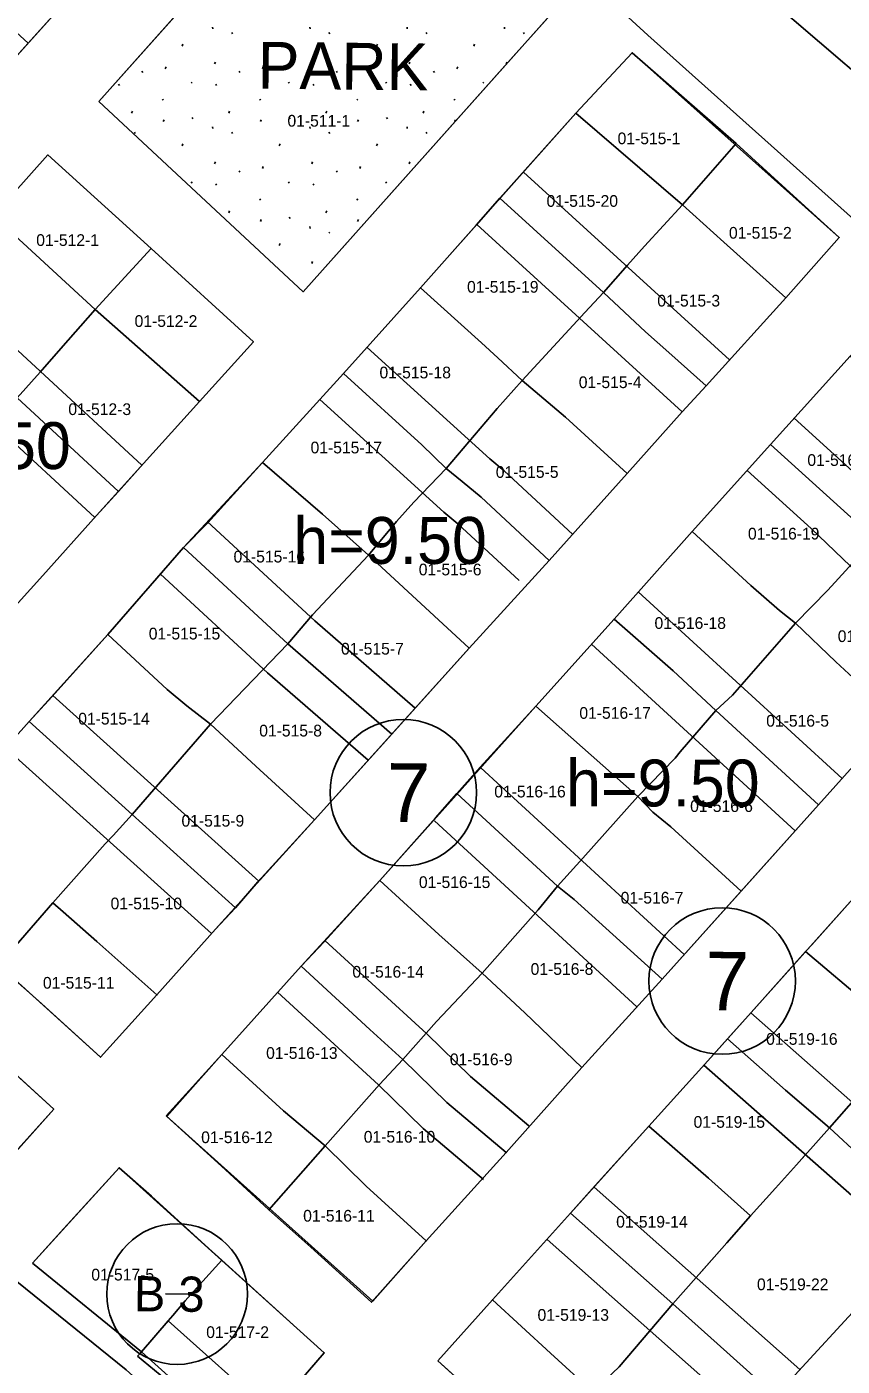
# Model space of a CAD drawing. Extents: x 413946 to 415528, y 4453939 to 4454944.
# Drawn here: x 415275 to 415344.5, y 4454500.5 to 4454614.8 of the extents above; entities that cross this region are included whole.
import ezdxf

# ---------------------------------------------------------------- set-up
doc = ezdxf.new("R2010")
doc.units = 0
for name, color, linetype in [('0_KADASTRO', 7, 'Continuous'), ('Level 27', 7, 'Continuous'), ('Level 28', 7, 'Continuous'), ('Level 30', 7, 'Continuous'), ('Level 32', 7, 'Continuous'), ('Level 41', 7, 'Continuous'), ('Level 58', 7, 'Continuous'), ('Level 59', 7, 'Continuous'), ('Level 62', 7, 'Continuous')]:
    doc.layers.add(name, color=color, linetype=linetype)

msp = doc.modelspace()

# ---------------------------------------------------------------- linework, layer by layer
at = {"layer": '0_KADASTRO'}
for points in [[(415281.1, 4454608.41), (415300.49, 4454630.14), (415303.6, 4454633.63), (415321.18, 4454617.54), (415316.45, 4454612.24), (415298.54, 4454592.17)], [(415264.52, 4454619), (415268.19, 4454623.21), (415271.06, 4454626.51), (415275.41, 4454622.61), (415279.81, 4454618.66), (415275.06, 4454613.36), (415273.08, 4454611.16)], [(415321.81, 4454607.4), (415326.6, 4454612.57), (415335.47, 4454604.83), (415330.89, 4454599.59)], [(415315.33, 4454600.15), (415321.81, 4454607.4), (415330.89, 4454599.59), (415327.65, 4454596.07), (415326.22, 4454594.45), (415324.15, 4454592.12)], [(415330.89, 4454599.59), (415335.47, 4454604.83), (415344.27, 4454596.8), (415339.71, 4454591.65), (415334.42, 4454596.39)], [(415272.09, 4454598.64), (415276.77, 4454603.85), (415285.57, 4454595.85), (415280.79, 4454590.65)], [(415308.54, 4454592.51), (415313.29, 4454597.85), (415315.33, 4454600.15), (415324.15, 4454592.12), (415322.56, 4454590.39), (415317.23, 4454584.6), (415315.14, 4454586.52), (415313.75, 4454587.8)], [(415324.15, 4454592.12), (415326.22, 4454594.45), (415327.65, 4454596.07), (415330.89, 4454599.59), (415334.42, 4454596.39), (415339.71, 4454591.65), (415332.91, 4454584.14), (415329.74, 4454586.98), (415327.75, 4454588.74)], [(415265.41, 4454591.2), (415267.45, 4454593.47), (415272.09, 4454598.64), (415280.79, 4454590.65), (415277.86, 4454587.32), (415276.1, 4454585.32), (415274.15, 4454583.11)], [(415280.79, 4454590.65), (415285.57, 4454595.85), (415294.3, 4454587.9), (415289.71, 4454582.81)], [(415301.97, 4454585.2), (415308.54, 4454592.51), (415313.75, 4454587.8), (415315.14, 4454586.52), (415317.23, 4454584.6), (415315.09, 4454582.21), (415310.75, 4454577.08), (415308.66, 4454579.12)], [(415317.23, 4454584.6), (415322.56, 4454590.39), (415324.15, 4454592.12), (415327.75, 4454588.74), (415329.74, 4454586.98), (415332.91, 4454584.14), (415330.87, 4454581.92), (415326.17, 4454576.67), (415320.92, 4454581.48)], [(415274.15, 4454583.11), (415276.1, 4454585.32), (415277.86, 4454587.32), (415280.79, 4454590.65), (415289.71, 4454582.81), (415284.92, 4454577.51), (415282.78, 4454575.13)], [(415338.41, 4454579.14), (415345.19, 4454586.67), (415352.4, 4454579.91), (415353.71, 4454578.68), (415347.21, 4454571), (415345.81, 4454572.43), (415345.58, 4454572.64)], [(415295.06, 4454577.59), (415301.97, 4454585.2), (415308.66, 4454579.12), (415310.75, 4454577.08), (415307.98, 4454574.21), (415306.51, 4454572.56), (415304.12, 4454569.7), (415300.18, 4454573.19)], [(415310.75, 4454577.08), (415315.09, 4454582.21), (415317.23, 4454584.6), (415320.92, 4454581.48), (415326.17, 4454576.67), (415319.51, 4454569.25), (415313.71, 4454574.63), (415312.09, 4454575.97)], [(415263.01, 4454570.8), (415260.8, 4454568.32), (415264.13, 4454565.29), (415266.34, 4454563.27), (415269.49, 4454560.4), (415276.32, 4454567.97), (415280.92, 4454573.07), (415282.78, 4454575.13), (415282.78, 4454575.13), (415282.78, 4454575.13), (415274.15, 4454583.11), (415270.75, 4454579.39), (415267.56, 4454575.9), (415264.2, 4454572.13)], [(415331.71, 4454571.7), (415338.41, 4454579.14), (415345.58, 4454572.64), (415345.81, 4454572.43), (415347.21, 4454571), (415343.29, 4454566.72), (415340.55, 4454563.89), (415339.16, 4454564.98), (415336.73, 4454567.11)], [(415288.34, 4454570.34), (415290.4, 4454572.44), (415295.06, 4454577.59), (415300.18, 4454573.19), (415304.12, 4454569.7), (415299.34, 4454564.59), (415297.22, 4454562.12), (415295.82, 4454563.43)], [(415304.12, 4454569.7), (415306.51, 4454572.56), (415307.98, 4454574.21), (415310.75, 4454577.08), (415312.09, 4454575.97), (415313.71, 4454574.63), (415319.51, 4454569.25), (415312.71, 4454561.76)], [(415325.06, 4454564.24), (415331.71, 4454571.7), (415336.73, 4454567.11), (415339.16, 4454564.98), (415340.55, 4454563.89), (415335.17, 4454557.74), (415333.75, 4454556.43), (415330.11, 4454559.82)], [(415281.87, 4454562.92), (415288.34, 4454570.34), (415295.82, 4454563.43), (415297.22, 4454562.12), (415290.64, 4454555.26), (415288.63, 4454556.85), (415286.94, 4454558.24)], [(415340.55, 4454563.89), (415343.29, 4454566.72), (415347.21, 4454571), (415350.59, 4454567.77), (415355.89, 4454563.36), (415349.15, 4454555.82), (415343.97, 4454560.6)], [(415297.22, 4454562.12), (415299.34, 4454564.59), (415304.12, 4454569.7), (415312.71, 4454561.76), (415306.1, 4454554.42)], [(415318.4, 4454556.81), (415325.06, 4454564.24), (415330.11, 4454559.82), (415333.75, 4454556.43), (415330.71, 4454552.92), (415330.28, 4454552.36), (415327.09, 4454549.11)], [(415333.75, 4454556.43), (415335.17, 4454557.74), (415340.55, 4454563.89), (415343.97, 4454560.6), (415349.15, 4454555.82), (415342.51, 4454548.4)], [(415275.17, 4454555.49), (415277.14, 4454557.64), (415281.87, 4454562.92), (415286.94, 4454558.24), (415288.63, 4454556.85), (415290.64, 4454555.26), (415283.96, 4454547.56)], [(415290.64, 4454555.26), (415297.22, 4454562.12), (415306.1, 4454554.42), (415299.5, 4454547.12), (415294.49, 4454551.68)], [(415311.65, 4454549.35), (415313.65, 4454551.59), (415318.4, 4454556.81), (415327.09, 4454549.11), (415322.41, 4454543.84), (415320.23, 4454541.46)], [(415263.74, 4454542.72), (415268.39, 4454547.93), (415275.17, 4454555.49), (415283.96, 4454547.56), (415282.32, 4454545.78), (415281.66, 4454545.07), (415277.2, 4454540.02), (415272.54, 4454534.71)], [(415327.09, 4454549.11), (415330.28, 4454552.36), (415330.71, 4454552.92), (415333.75, 4454556.43), (415342.51, 4454548.4), (415335.9, 4454541.03), (415329.91, 4454546.51), (415328.37, 4454547.75)], [(415283.96, 4454547.56), (415290.64, 4454555.26), (415294.49, 4454551.68), (415299.5, 4454547.12), (415294.67, 4454541.81), (415292.77, 4454539.6)], [(415305.09, 4454541.94), (415309.83, 4454547.27), (415311.65, 4454549.35), (415320.23, 4454541.46), (415318.58, 4454539.44), (415313.8, 4454534.03), (415310.1, 4454537.32)], [(415320.23, 4454541.46), (415322.41, 4454543.84), (415327.09, 4454549.11), (415328.37, 4454547.75), (415329.91, 4454546.51), (415335.9, 4454541.03), (415329.15, 4454533.51), (415321.67, 4454540.3)], [(415277.2, 4454540.02), (415281.66, 4454545.07), (415282.32, 4454545.78), (415283.96, 4454547.56), (415292.77, 4454539.6), (415291.06, 4454537.79), (415286.06, 4454532.17), (415280.93, 4454536.74), (415278.08, 4454539.25)], [(415341.4, 4454535.86), (415341.92, 4454536.44), (415346.16, 4454541.18), (415348.08, 4454543.29), (415352.98, 4454538.72), (415356.69, 4454535.4), (415354.88, 4454533.47), (415350.02, 4454528.33), (415346.7, 4454531.38)], [(415298.37, 4454534.61), (415300.32, 4454536.7), (415305.09, 4454541.94), (415310.1, 4454537.32), (415313.8, 4454534.03), (415309.92, 4454529.9), (415307.04, 4454526.66), (415304.24, 4454529.22)], [(415313.8, 4454534.03), (415318.58, 4454539.44), (415320.23, 4454541.46), (415321.67, 4454540.3), (415329.15, 4454533.51), (415327.16, 4454531.33), (415322.3, 4454525.96), (415317.45, 4454530.63)], [(415272.54, 4454534.71), (415277.2, 4454540.02), (415278.08, 4454539.25), (415280.93, 4454536.74), (415286.06, 4454532.17), (415281.26, 4454526.85), (415276.21, 4454531.43), (415273.47, 4454533.88)], [(415334.73, 4454528.41), (415336.75, 4454530.66), (415341.4, 4454535.86), (415346.7, 4454531.38), (415350.02, 4454528.33), (415343.44, 4454520.82), (415339.68, 4454524.05)], [(415291.59, 4454527.07), (415298.37, 4454534.61), (415304.24, 4454529.22), (415307.04, 4454526.66), (415305.05, 4454524.51), (415300.43, 4454519.28), (415296.85, 4454522.27)], [(415307.04, 4454526.66), (415309.92, 4454529.9), (415313.8, 4454534.03), (415317.45, 4454530.63), (415322.3, 4454525.96), (415315.86, 4454518.71), (415310.8, 4454522.99)], [(415260.25, 4454521.48), (415262.84, 4454524.11), (415268.59, 4454530.33), (415269.76, 4454529.25), (415272.17, 4454527.05), (415277.27, 4454522.42), (415272.6, 4454517.21), (415269.64, 4454513.87)], [(415328.03, 4454520.98), (415332.79, 4454526.26), (415334.73, 4454528.41), (415339.68, 4454524.05), (415343.44, 4454520.82), (415341.32, 4454518.46), (415340.61, 4454517.67), (415338.82, 4454515.67), (415336.69, 4454513.32), (415333.11, 4454516.54)], [(415343.44, 4454520.82), (415350.02, 4454528.33), (415358.94, 4454520.32), (415354.15, 4454514.93), (415352.33, 4454512.88), (415346.15, 4454518.33)], [(415286.9, 4454521.8), (415291.59, 4454527.07), (415296.85, 4454522.27), (415300.43, 4454519.28), (415295.61, 4454513.84), (415291.88, 4454517.27)], [(415300.43, 4454519.28), (415305.05, 4454524.51), (415307.04, 4454526.66), (415310.8, 4454522.99), (415315.86, 4454518.71), (415309.04, 4454511.18), (415303.91, 4454515.86)], [(415321.35, 4454513.54), (415323.19, 4454515.61), (415328.03, 4454520.98), (415333.11, 4454516.54), (415336.69, 4454513.32), (415334.67, 4454511.02), (415332.05, 4454508.05), (415330.07, 4454505.8)], [(415341.28, 4454518.41), (415340.61, 4454517.67), (415338.82, 4454515.67), (415336.69, 4454513.32), (415334.67, 4454511.02), (415332.54, 4454508.6), (415332.05, 4454508.05), (415330.07, 4454505.8), (415333.85, 4454502.42), (415338.85, 4454497.94), (415340.8, 4454500.07), (415345.71, 4454505.4), (415352.33, 4454512.88), (415346.15, 4454518.33), (415343.44, 4454520.82), (415341.32, 4454518.46)], [(415295.61, 4454513.84), (415300.43, 4454519.28), (415303.91, 4454515.86), (415309.04, 4454511.18), (415304.38, 4454505.94), (415299.18, 4454510.63)], [(415275.45, 4454509.28), (415284.74, 4454501.7), (415287.02, 4454504.37), (415287.41, 4454504.82), (415288.47, 4454506.05), (415289.44, 4454507.13), (415291.61, 4454509.52), (415290.5, 4454510.53), (415285.61, 4454514.99), (415282.84, 4454517.42), (415278.13, 4454512.24)], [(415314.69, 4454506.15), (415321.35, 4454513.54), (415330.07, 4454505.8), (415325.5, 4454500.43), (415323.26, 4454498.3), (415319.65, 4454501.61)], [(415287.02, 4454504.37), (415287.41, 4454504.82), (415288.47, 4454506.05), (415289.44, 4454507.13), (415291.61, 4454509.52), (415298, 4454503.73), (415300.34, 4454501.63), (415295.86, 4454496.44)], [(415310.02, 4454500.93), (415314.69, 4454506.15), (415319.65, 4454501.61), (415323.26, 4454498.3), (415318.7, 4454493.11)], [(415323.26, 4454498.3), (415325.5, 4454500.43), (415330.07, 4454505.8), (415333.85, 4454502.42), (415338.85, 4454497.94), (415336.86, 4454495.7), (415332.18, 4454490.43)], [(415284.42, 4454501.33), (415284.64, 4454501.58), (415284.74, 4454501.7), (415287.02, 4454504.37), (415295.86, 4454496.44), (415293.58, 4454493.77)]]:
    msp.add_lwpolyline(points, close=True, dxfattribs=at)
at = {"layer": 'Level 27'}
for p, q in [((415326.6, 4454612.57), (415344.27, 4454596.8)), ((415298.54, 4454592.17), (415281.1, 4454608.41)), ((415281.26, 4454526.85), (415263.74, 4454542.72)), ((415259.8, 4454538.31), (415277.27, 4454522.42)), ((415304.47, 4454506.04), (415286.85, 4454521.84)), ((415282.84, 4454517.42), (415300.34, 4454501.63)), ((415327.52, 4454485.21), (415310.02, 4454500.93))]:
    msp.add_line(p, q, dxfattribs=at)
for points in [[(415263.74, 4454542.72), (415268.39, 4454547.93), (415275.17, 4454555.49), (415281.87, 4454562.92), (415288.34, 4454570.34), (415295.06, 4454577.59), (415301.97, 4454585.2), (415308.54, 4454592.51), (415321.81, 4454607.4), (415326.6, 4454612.57)], [(415240.66, 4454563.64), (415245.43, 4454568.95), (415250.05, 4454574.1), (415254.04, 4454578.54), (415265.41, 4454591.2), (415267.45, 4454593.47), (415272.09, 4454598.64), (415276.77, 4454603.85), (415285.57, 4454595.85), (415294.3, 4454587.9), (415289.71, 4454582.81), (415284.92, 4454577.51), (415280.92, 4454573.07), (415276.32, 4454567.97), (415269.49, 4454560.4), (415262.86, 4454553.06), (415258.15, 4454547.84)], [(415344.27, 4454596.8), (415339.71, 4454591.65), (415332.91, 4454584.14), (415330.87, 4454581.92), (415326.17, 4454576.67), (415319.51, 4454569.25), (415312.71, 4454561.76), (415299.5, 4454547.12), (415291.06, 4454537.79), (415286.06, 4454532.17), (415281.26, 4454526.85)], [(415286.85, 4454521.84), (415291.59, 4454527.07), (415298.37, 4454534.61), (415305.09, 4454541.94), (415318.4, 4454556.81), (415325.06, 4454564.24), (415331.71, 4454571.7), (415338.41, 4454579.14), (415345.19, 4454586.67), (415349.81, 4454591.81)], [(415367.29, 4454575.96), (415362.62, 4454570.74), (415355.89, 4454563.36), (415349.15, 4454555.82), (415342.51, 4454548.4), (415329.15, 4454533.51), (415322.3, 4454525.96), (415315.86, 4454518.71), (415309.04, 4454511.18), (415304.47, 4454506.04)], [(415310.02, 4454500.93), (415314.69, 4454506.15), (415321.35, 4454513.54), (415328.03, 4454520.98), (415332.79, 4454526.26), (415336.75, 4454530.66), (415346.16, 4454541.18), (415354.8, 4454550.86), (415361.66, 4454558.38), (415368.28, 4454565.86), (415372.83, 4454571.21)], [(415390.31, 4454555.19), (415385.34, 4454549.56), (415378.94, 4454542.48), (415372.27, 4454535.1), (415363.68, 4454525.56), (415358.94, 4454520.32), (415352.33, 4454512.88), (415345.71, 4454505.4), (415340.8, 4454500.07), (415336.86, 4454495.7), (415332.18, 4454490.43), (415327.52, 4454485.21)], [(415277.27, 4454522.42), (415269.59, 4454513.91)], [(415275.45, 4454509.28), (415282.84, 4454517.42)], [(415293.57, 4454493.78), (415284.74, 4454501.7), (415275.45, 4454509.28)], [(415300.34, 4454501.63), (415293.57, 4454493.78)]]:
    msp.add_lwpolyline(points, dxfattribs=at)
at = {"layer": 'Level 28'}
for p, q in [((415281.1, 4454608.41), (415303.6, 4454633.63)), ((415321.18, 4454617.54), (415298.54, 4454592.17))]:
    msp.add_line(p, q, dxfattribs=at)
msp.add_lwpolyline([(415297.91, 4454638.85), (415293.18, 4454633.57), (415286.52, 4454626.14), (415279.81, 4454618.66), (415273.91, 4454612.08)], dxfattribs=at)
at = {"layer": 'Level 32'}
msp.add_line((415288.79, 4454506.63), (415286.79, 4454506.65), dxfattribs=at)
msp.add_circle((415287.79, 4454506.64), 6, dxfattribs=at)
at = {"layer": 'Level 41'}
for p, q in [((415290.82, 4454614.76), (415290.83, 4454614.6)), ((415292.45, 4454614.29), (415292.52, 4454614.18)), ((415299.11, 4454614.76), (415299.13, 4454614.6)), ((415300.74, 4454614.29), (415300.81, 4454614.18)), ((415307.4, 4454614.76), (415307.42, 4454614.6)), ((415309.03, 4454614.29), (415309.1, 4454614.18)), ((415315.7, 4454614.76), (415315.71, 4454614.6)), ((415317.33, 4454614.29), (415317.4, 4454614.18)), ((415288.21, 4454613.14), (415288.28, 4454613.3)), ((415296.5, 4454613.14), (415296.57, 4454613.3)), ((415304.79, 4454613.14), (415304.87, 4454613.3)), ((415313.09, 4454613.14), (415313.16, 4454613.3)), ((415290.98, 4454611.61), (415291.05, 4454611.77)), ((415299.27, 4454611.61), (415299.34, 4454611.77)), ((415307.57, 4454611.61), (415307.64, 4454611.77)), ((415315.86, 4454611.61), (415315.93, 4454611.77)), ((415284.78, 4454611), (415284.85, 4454610.89)), ((415286.77, 4454611.2), (415286.84, 4454611.36)), ((415293.08, 4454611), (415293.15, 4454610.89)), ((415295.06, 4454611.2), (415295.14, 4454611.36)), ((415301.37, 4454611), (415301.44, 4454610.89)), ((415303.36, 4454611.2), (415303.43, 4454611.36)), ((415309.66, 4454611), (415309.73, 4454610.89)), ((415311.65, 4454611.2), (415311.72, 4454611.36)), ((415282.8, 4454609.88), (415282.87, 4454609.77)), ((415288.99, 4454610.07), (415289.06, 4454609.96)), ((415291.09, 4454609.88), (415291.16, 4454609.77)), ((415297.28, 4454610.07), (415297.35, 4454609.96)), ((415299.38, 4454609.88), (415299.45, 4454609.77)), ((415305.58, 4454610.07), (415305.65, 4454609.96)), ((415307.68, 4454609.88), (415307.75, 4454609.77)), ((415313.87, 4454610.07), (415313.94, 4454609.96)), ((415286.54, 4454608.61), (415286.61, 4454608.51)), ((415294.83, 4454608.61), (415294.9, 4454608.51)), ((415303.12, 4454608.61), (415303.19, 4454608.51)), ((415311.41, 4454608.61), (415311.48, 4454608.51)), ((415283.89, 4454607.42), (415283.97, 4454607.58)), ((415286.59, 4454606.69), (415286.67, 4454606.85)), ((415289.06, 4454607.04), (415289.13, 4454606.93)), ((415292.19, 4454607.42), (415292.26, 4454607.58)), ((415294.89, 4454606.69), (415294.96, 4454606.85)), ((415297.35, 4454607.04), (415297.42, 4454606.93)), ((415300.48, 4454607.42), (415300.55, 4454607.58)), ((415303.18, 4454606.69), (415303.25, 4454606.85)), ((415305.64, 4454607.04), (415305.72, 4454606.93)), ((415308.77, 4454607.42), (415308.84, 4454607.58)), ((415311.47, 4454606.69), (415311.54, 4454606.85)), ((415284.15, 4454605.78), (415284.22, 4454605.67)), ((415290.82, 4454606.25), (415290.83, 4454606.09)), ((415292.45, 4454605.78), (415292.52, 4454605.67)), ((415299.11, 4454606.25), (415299.13, 4454606.09)), ((415300.74, 4454605.78), (415300.81, 4454605.67)), ((415307.4, 4454606.25), (415307.42, 4454606.09)), ((415309.03, 4454605.78), (415309.1, 4454605.67)), ((415288.21, 4454604.63), (415288.28, 4454604.79)), ((415296.5, 4454604.63), (415296.57, 4454604.79)), ((415304.79, 4454604.63), (415304.87, 4454604.79)), ((415290.98, 4454603.1), (415291.05, 4454603.26)), ((415293.08, 4454602.49), (415293.15, 4454602.38)), ((415295.06, 4454602.69), (415295.14, 4454602.85)), ((415299.27, 4454603.1), (415299.34, 4454603.26)), ((415301.37, 4454602.49), (415301.44, 4454602.38)), ((415303.36, 4454602.69), (415303.43, 4454602.85)), ((415307.57, 4454603.1), (415307.64, 4454603.26)), ((415288.99, 4454601.56), (415289.06, 4454601.45)), ((415291.09, 4454601.37), (415291.16, 4454601.26)), ((415297.28, 4454601.56), (415297.35, 4454601.45)), ((415299.38, 4454601.37), (415299.45, 4454601.26)), ((415305.58, 4454601.56), (415305.65, 4454601.45)), ((415294.83, 4454600.1), (415294.9, 4454600)), ((415303.12, 4454600.1), (415303.19, 4454600)), ((415292.19, 4454598.91), (415292.26, 4454599.07)), ((415300.48, 4454598.91), (415300.55, 4454599.07)), ((415294.89, 4454598.18), (415294.96, 4454598.34)), ((415297.35, 4454598.53), (415297.42, 4454598.42)), ((415299.11, 4454597.74), (415299.13, 4454597.58)), ((415303.18, 4454598.18), (415303.25, 4454598.34)), ((415300.74, 4454597.27), (415300.81, 4454597.16)), ((415296.5, 4454596.12), (415296.57, 4454596.28)), ((415299.27, 4454594.59), (415299.34, 4454594.75))]:
    msp.add_line(p, q, dxfattribs=at)
at = {"layer": 'Level 58'}
for centre in [(415307.08, 4454549.43), (415334.28, 4454533.35)]:
    msp.add_circle(centre, 6.25, dxfattribs=at)
at = {"layer": 'Level 59'}
for points in [[(415258.8, 4454628.31), (415275.09, 4454613.39)], [(415317.34, 4454602.38), (415334.92, 4454586.36)], [(415313.34, 4454597.9), (415330.88, 4454581.93)], [(415284.79, 4454577.36), (415267.41, 4454593.43)], [(415280.77, 4454572.9), (415263.4, 4454588.96)], [(415303.99, 4454587.42), (415314.47, 4454577.9)], [(415299.95, 4454582.98), (415310.53, 4454573.37)], [(415346.02, 4454576.29), (415340.42, 4454581.37)], [(415314.47, 4454577.9), (415315.69, 4454576.88)], [(415315.69, 4454576.88), (415321.55, 4454571.45)], [(415341.86, 4454571.97), (415336.4, 4454576.91)], [(415290.38, 4454572.54), (415299.53, 4454564.09)], [(415310.53, 4454573.37), (415311.72, 4454572.38)], [(415311.72, 4454572.38), (415316.96, 4454567.52)], [(415348.59, 4454565.53), (415341.86, 4454571.97)], [(415286.37, 4454568.08), (415295.5, 4454559.64)], [(415327.13, 4454566.57), (415344.51, 4454550.63)], [(415299.53, 4454564.09), (415308.1, 4454556.65)], [(415323.13, 4454562.09), (415340.51, 4454546.17)], [(415295.5, 4454559.64), (415304.08, 4454552.2)], [(415277.18, 4454557.72), (415294.75, 4454541.87)], [(415273.16, 4454553.26), (415290.73, 4454537.42)], [(415313.69, 4454551.55), (415331.03, 4454535.61)], [(415309.75, 4454547.02), (415327.01, 4454531.15)], [(415300.4, 4454536.82), (415309.1, 4454528.84)], [(415296.34, 4454532.4), (415304.97, 4454524.49)], [(415336.73, 4454530.64), (415354.32, 4454515.12)], [(415312.82, 4454525.21), (415309.1, 4454528.84)], [(415332.72, 4454526.18), (415350.34, 4454510.64)], [(415317.8, 4454521), (415312.82, 4454525.21)], [(415308.79, 4454520.76), (415304.97, 4454524.49)], [(415313.92, 4454516.42), (415308.79, 4454520.76)], [(415323.35, 4454515.77), (415340.91, 4454500.19)], [(415319.34, 4454511.31), (415336.89, 4454495.74)]]:
    msp.add_lwpolyline(points, dxfattribs=at)
at = {"layer": 'Level 62'}
for p, q in [((415351.95, 4454605.45), (415332.29, 4454622.3)), ((415327.93, 4454614.06), (415351.15, 4454593.29))]:
    msp.add_line(p, q, dxfattribs=at)
for points in [[(415304.96, 4454635.11), (415327.93, 4454614.06)], [(415288.76, 4454495.41), (415283.44, 4454500.18), (415268.32, 4454512.37)]]:
    msp.add_lwpolyline(points, dxfattribs=at)

# ---------------------------------------------------------------- texts
at = {"layer": '0_KADASTRO'}
for s, p in [('01-511-1', (415297.2, 4454606.26)), ('01-515-1', (415325.36, 4454604.76)), ('01-515-20', (415319.3, 4454599.42)), ('01-515-2', (415334.86, 4454596.7)), ('01-512-1', (415275.77, 4454596.08)), ('01-515-19', (415312.52, 4454592.09)), ('01-515-3', (415328.75, 4454590.91)), ('01-512-2', (415284.16, 4454589.17)), ('01-515-18', (415305.05, 4454584.78)), ('01-515-4', (415322.05, 4454583.95)), ('01-512-3', (415278.51, 4454581.65)), ('01-515-17', (415299.17, 4454578.38)), ('01-516-20', (415341.55, 4454577.31)), ('01-515-5', (415314.97, 4454576.29)), ('01-516-19', (415336.48, 4454571.03)), ('01-515-16', (415292.6, 4454569.07)), ('01-515-6', (415308.4, 4454567.97)), ('01-515-15', (415285.37, 4454562.5)), ('01-516-18', (415328.51, 4454563.4)), ('01-516-4', (415344.14, 4454562.28)), ('01-515-7', (415301.77, 4454561.21)), ('01-516-17', (415322.1, 4454555.73)), ('01-515-14', (415279.35, 4454555.24)), ('01-516-5', (415338.04, 4454555.06)), ('01-515-8', (415294.79, 4454554.22)), ('01-516-16', (415314.84, 4454549.02)), ('01-516-6', (415331.55, 4454547.78)), ('01-515-9', (415288.16, 4454546.53)), ('01-516-15', (415308.41, 4454541.29)), ('01-516-7', (415325.62, 4454539.96)), ('01-515-10', (415282.11, 4454539.47)), ('01-516-8', (415317.94, 4454533.88)), ('01-515-11', (415276.34, 4454532.7)), ('01-516-14', (415302.74, 4454533.64)), ('01-519-16', (415338.03, 4454527.91)), ('01-516-13', (415295.38, 4454526.71)), ('01-516-9', (415311.05, 4454526.17)), ('01-519-15', (415331.84, 4454520.83)), ('01-516-12', (415289.84, 4454519.52)), ('01-516-10', (415303.71, 4454519.56)), ('01-516-11', (415298.54, 4454512.82)), ('01-519-14', (415325.24, 4454512.31)), ('01-517-5', (415280.47, 4454507.8)), ('01-519-22', (415337.25, 4454506.97)), ('01-519-13', (415318.53, 4454504.36)), ('01-517-2', (415290.27, 4454502.89))]:
    msp.add_text(s, height=1, dxfattribs=at).set_placement(p)
at = {"layer": 'Level 30'}
for p in [(415262.21, 4454577.04), (415297.7, 4454568.95), (415320.97, 4454548.25)]:
    msp.add_text('h=9.50', height=4, dxfattribs=at).set_placement(p)
at = {"layer": 'Level 32'}
msp.add_text('B 3', height=3, rotation=359.4141, dxfattribs=at).set_placement((415284.09, 4454505.18))
at = {"layer": 'Level 41'}
msp.add_text('PARK', height=4, rotation=359.4141, dxfattribs=at).set_placement((415294.64, 4454609.5))
at = {"layer": 'Level 58'}
for p in [(415305.63, 4454546.95), (415332.83, 4454530.86)]:
    msp.add_text('7', height=5, rotation=359.4141, dxfattribs=at).set_placement(p)

doc.saveas('drawing.dxf')
